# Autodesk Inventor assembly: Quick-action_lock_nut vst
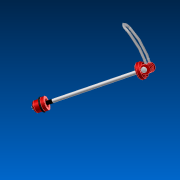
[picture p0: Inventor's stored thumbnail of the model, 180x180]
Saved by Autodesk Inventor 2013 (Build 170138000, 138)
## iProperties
Shininess: 20.0
Length Units: 11269
Angle Units: 11279
Time Units: 11290
Mass Units: 11283
Length Display Precision: 3
Angle Display Precision: 2
Created: 2001-04
Part Number: Quick-action_lock_nut vst
Document SubType Name: Baugruppe
Designer: dl
Density: 0.0
Volumn: 0.0
Area: 0.0
PropertySet Name: Model Information
Control State: 0
Master: False
Checked Out: False
Author: dl
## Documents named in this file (3)
- C:\Webworld\Webworld2014\ATC2013\Assemblies\ATC-Baby Carriage\3-FRONT WHEEL\Quick-action_lock_nut vst.iam
- C:\Webworld\Webworld2014\ATC2013\Assemblies\ATC-Baby Carriage\3-FRONT WHEEL\Nut vst.iam
- C:\Webworld\Webworld2014\ATC2013\Assemblies\ATC-Baby Carriage\3-FRONT WHEEL\Turnbuckle.iam
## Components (2 placed, 2 different names)
1. Turnbuckle:1 [sub-assembly] — Mate:1, Mate:2
2. Nut vst:1 [sub-assembly] — Mate:1, Mate:2
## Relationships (2: Mate 2)
- Mate:1: Turnbuckle:1 ↔ Nut vst:1
- Mate:2: Turnbuckle:1 ↔ Nut vst:1
